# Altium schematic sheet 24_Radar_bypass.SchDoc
size 289 x 396 mm
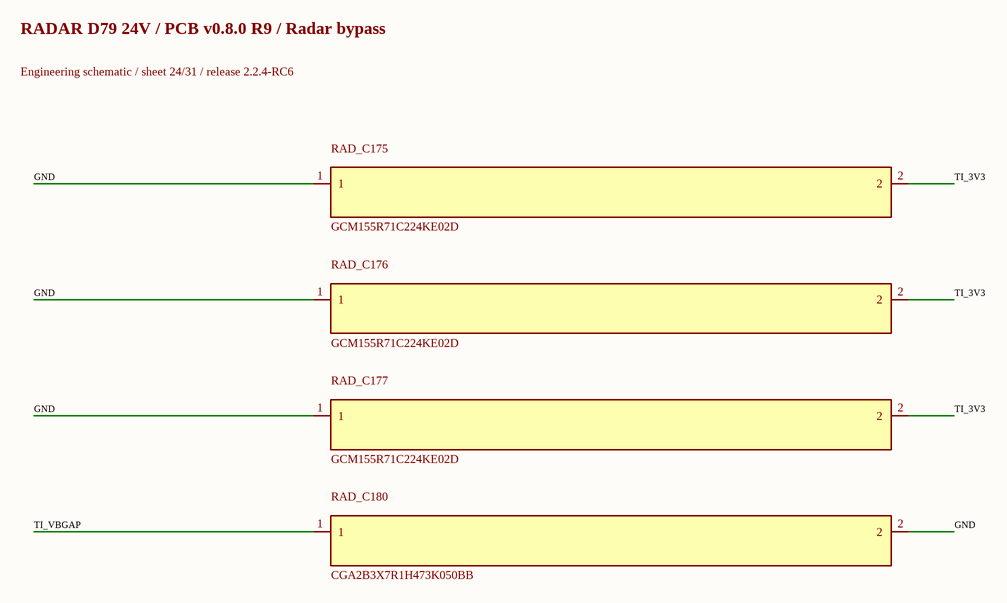
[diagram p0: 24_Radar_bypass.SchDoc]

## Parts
RAD_C175  GCM155R71C224KE02D  [0402L]
RAD_C176  GCM155R71C224KE02D  [0402L]
RAD_C177  GCM155R71C224KE02D  [0402L]
RAD_C180  CGA2B3X7R1H473K050BB  [0402L]

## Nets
GND: RAD_C175.1 RAD_C176.1 RAD_C177.1 RAD_C180.2
TI_3V3: RAD_C175.2 RAD_C176.2 RAD_C177.2
TI_VBGAP: RAD_C180.1

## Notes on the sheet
- RADAR D79 24V / PCB v0.8.0 R9 / Radar bypass
- Engineering schematic / sheet 24/31 / release 2.2.4-RC6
